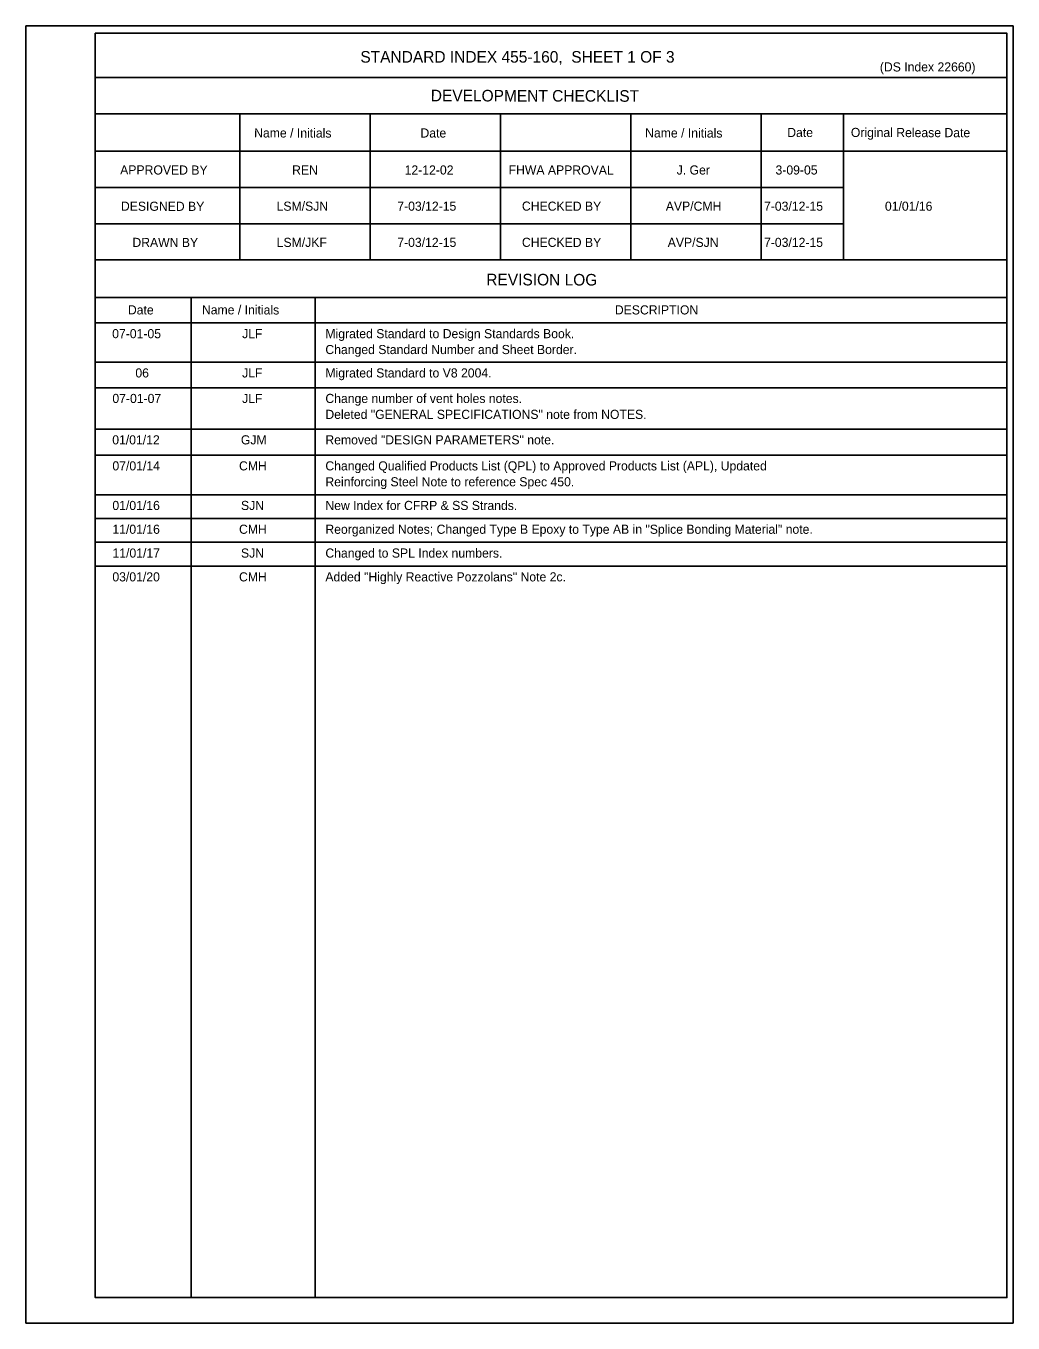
# Model space of a CAD drawing. Extents: x 120462 to 120592, y 120515 to 120635.
# Drawn here: x 120570.2 to 120592.01, y 120600.69 to 120629.36 of the extents above; entities that cross this region are included whole.
import ezdxf

# ---------------------------------------------------------------- set-up
doc = ezdxf.new("R2010")
doc.units = 0
for name, color, linetype in [('AdhocPoint_dp', 7, 'Continuous'), ('Border', 7, 'Continuous'), ('SheetBorder_dp', 7, 'Continuous')]:
    doc.layers.add(name, color=color, linetype=linetype)

msp = doc.modelspace()

# ---------------------------------------------------------------- linework, layer by layer
at = {"layer": 'AdhocPoint_dp'}
for p, q in [((120571.728, 120621.929), (120591.874, 120621.929)), ((120571.728, 120621.365), (120591.874, 120621.365)), ((120571.728, 120620.45), (120591.874, 120620.45)), ((120571.728, 120619.875), (120591.874, 120619.875)), ((120571.728, 120619), (120591.874, 120619)), ((120571.728, 120618.474), (120591.874, 120618.474)), ((120571.728, 120617.948), (120591.874, 120617.948)), ((120571.728, 120617.422), (120591.874, 120617.422))]:
    msp.add_line(p, q, dxfattribs=at)
at = {"layer": 'Border'}
for p, q in [((120591.874, 120628.217), (120571.727, 120628.217)), ((120591.874, 120627.417), (120571.727, 120627.417)), ((120574.927, 120627.417), (120574.927, 120624.189)), ((120577.807, 120627.417), (120577.807, 120624.189)), ((120580.687, 120627.417), (120580.687, 120624.189)), ((120583.567, 120627.417), (120583.567, 120624.189)), ((120586.447, 120627.417), (120586.447, 120624.189)), ((120588.262, 120627.417), (120588.262, 120624.189)), ((120591.874, 120626.589), (120571.727, 120626.589)), ((120588.262, 120625.789), (120571.727, 120625.789)), ((120588.262, 120624.989), (120571.727, 120624.989)), ((120591.874, 120624.189), (120571.727, 120624.189)), ((120591.874, 120623.361), (120571.727, 120623.361)), ((120573.848, 120623.361), (120573.848, 120601.255)), ((120576.59, 120623.361), (120576.59, 120601.255)), ((120591.874, 120622.797), (120571.727, 120622.797))]:
    msp.add_line(p, q, dxfattribs=at)
msp.add_lwpolyline([(120571.728, 120629.197), (120591.874, 120629.197), (120591.874, 120601.255), (120571.728, 120601.255)], close=True, dxfattribs=at)
at = {"layer": 'SheetBorder_dp'}
msp.add_line((120570.197, 120600.693), (120570.197, 120600.693), dxfattribs=at)
msp.add_lwpolyline([(120570.197, 120629.36), (120592.01, 120629.36), (120592.01, 120600.693), (120570.197, 120600.693)], close=True, dxfattribs=at)

# ---------------------------------------------------------------- texts
at = {"layer": 'Border'}
for s, height, p in [('STANDARD INDEX 455-160,  SHEET 1 OF 3', 0.256, (120577.587, 120628.549)), ('(DS Index 22660)', 0.2016, (120589.067, 120628.354)), ('REN', 0.2016, (120576.079, 120626.076)), ('12-12-02', 0.2016, (120578.566, 120626.076)), ('J. Ger', 0.2016, (120584.577, 120626.076)), ('3-09-05', 0.2016, (120586.761, 120626.076)), ('LSM/SJN', 0.2016, (120575.736, 120625.276)), ('7-03/12-15', 0.2016, (120578.403, 120625.276)), ('AVP/CMH', 0.2016, (120584.336, 120625.276)), ('7-03/12-15', 0.2016, (120586.507, 120625.276)), ('01/01/16', 0.2016, (120589.179, 120625.276)), ('LSM/JKF', 0.2016, (120575.738, 120624.476)), ('7-03/12-15', 0.2016, (120578.403, 120624.476)), ('AVP/SJN', 0.2016, (120584.379, 120624.476)), ('7-03/12-15', 0.2016, (120586.507, 120624.476)), ('DESCRIPTION', 0.2016, (120583.211, 120622.984)), ('07-01-05', 0.2016, (120572.103, 120622.459)), ('JLF', 0.2016, (120574.974, 120622.459)), ('Migrated Standard to Design Standards Book.', 0.2016, (120576.814, 120622.459)), ('Changed Standard Number and Sheet Border.', 0.2016, (120576.814, 120622.108)), ('06', 0.2016, (120572.615, 120621.591)), ('JLF', 0.2016, (120574.974, 120621.591)), ('Migrated Standard to V8 2004.', 0.2016, (120576.814, 120621.591)), ('07-01-07', 0.2016, (120572.107, 120621.027)), ('JLF', 0.2016, (120574.974, 120621.027)), ('Change number of vent holes notes.', 0.2016, (120576.814, 120621.027)), ('Deleted "GENERAL SPECIFICATIONS" note from NOTES.', 0.2016, (120576.814, 120620.675)), ('01/01/12', 0.2016, (120572.104, 120620.112)), ('GJM', 0.2016, (120574.947, 120620.112)), ('Removed "DESIGN PARAMETERS" note.', 0.2016, (120576.814, 120620.112)), ('07/01/14', 0.2016, (120572.108, 120619.537)), ('CMH', 0.2016, (120574.906, 120619.537)), ('Changed Qualified Products List (QPL) to Approved Products List (APL), Updated', 0.2016, (120576.814, 120619.537)), ('Reinforcing Steel Note to reference Spec 450.', 0.2016, (120576.814, 120619.185)), ('01/01/16', 0.2016, (120572.107, 120618.662)), ('SJN', 0.2016, (120574.949, 120618.662)), ('New Index for CFRP & SS Strands.', 0.2016, (120576.814, 120618.662)), ('11/01/16', 0.2016, (120572.107, 120618.136)), ('CMH', 0.2016, (120574.906, 120618.136)), ('Reorganized Notes; Changed Type B Epoxy to Type AB in "Splice Bonding Material" note.', 0.2016, (120576.814, 120618.136)), ('11/01/17', 0.2016, (120572.109, 120617.61)), ('SJN', 0.2016, (120574.949, 120617.61)), ('Changed to SPL Index numbers.', 0.2016, (120576.814, 120617.61)), ('03/01/20', 0.2016, (120572.107, 120617.084)), ('CMH', 0.2016, (120574.906, 120617.084)), ('Added "Highly Reactive Pozzolans" Note 2c.', 0.2016, (120576.814, 120617.084))]:
    msp.add_text(s, height=height, dxfattribs=at).set_placement(p)
for s, height, p in [('DEVELOPMENT CHECKLIST', 0.256, (120579.143, 120627.694)), ('Name / Initials', 0.2016, (120575.24, 120626.896)), ('Date', 0.2016, (120578.915, 120626.894)), ('Name / Initials', 0.2016, (120583.88, 120626.896)), ('Date', 0.2016, (120587.02, 120626.906)), ('Original Release Date', 0.2016, (120588.426, 120626.906)), ('APPROVED BY', 0.2016, (120572.279, 120626.078)), ('FHWA APPROVAL', 0.2016, (120580.863, 120626.078)), ('DESIGNED BY', 0.2016, (120572.296, 120625.276)), ('CHECKED BY', 0.2016, (120581.157, 120625.278)), ('DRAWN BY', 0.2016, (120572.549, 120624.476)), ('CHECKED BY', 0.2016, (120581.157, 120624.478)), ('REVISION LOG', 0.256, (120580.369, 120623.628)), ('Date', 0.2016, (120572.45, 120622.985)), ('Name / Initials', 0.2016, (120574.086, 120622.987))]:
    msp.add_text(s, height=height, rotation=359.8756, dxfattribs=at).set_placement(p)

doc.saveas('drawing.dxf')
